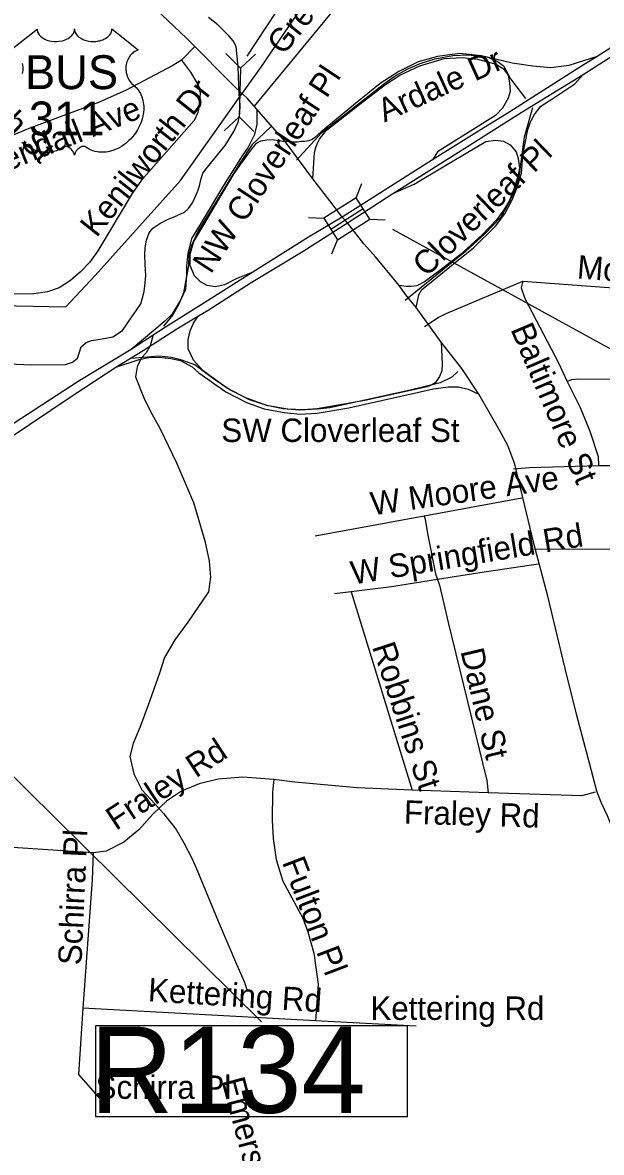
# Model space of a CAD drawing. Extents: x 1662474 to 1856135, y 779280 to 917889.
# Drawn here: x 1705150 to 1707499, y 792888 to 797474 of the extents above; entities that cross this region are included whole.
import ezdxf

# ---------------------------------------------------------------- set-up
doc = ezdxf.new("R2010")
doc.units = 0
for name, color, linetype in [('Exist Hydrographic Creek Single Shore', 7, 'Continuous'), ('Exist Hydrographic Misc Water Feature', 7, 'Continuous'), ('Exist Railroad Structure Bridge Number Label', 7, 'Continuous'), ('Exist Road Non-System Type 51', 7, 'Continuous'), ('Exist Road Non-System Type 51 Label', 7, 'Continuous'), ('Exist Road Primary Interstate Divided Center Attributed', 7, 'Continuous'), ('Exist Road Primary Interstate Ramp 1 Lane Attributed', 7, 'Continuous'), ('Exist Road Primary Interstate Structure Standard Bridge CELL', 7, 'Continuous'), ('Exist Road Primary Interstate Structure Standard Bridge Number Label', 7, 'Continuous'), ('Exist Road Primary US Shield CELL', 7, 'Continuous'), ('Exist Road Primary US Shield Number Label', 7, 'Continuous'), ('Exist Road Primary US Structure Pipe CELL', 7, 'Continuous'), ('Exist Road Primary US Structure Pipe Number Label', 7, 'Continuous'), ('Exist Road Primary US UnDivided 4 Lane Attributed', 7, 'Continuous'), ('Exist Utilities Electrical Transmission Line', 7, 'Continuous')]:
    doc.layers.add(name, color=color, linetype=linetype)

msp = doc.modelspace()

# ---------------------------------------------------------------- linework, layer by layer
at = {"layer": 'Exist Hydrographic Creek Single Shore'}
msp.add_lwpolyline([(1705094.1, 796088.5), (1705185.5, 796084.1), (1705324.2, 796085.9), (1705352.1, 796094.8), (1705371.8, 796111.3), (1705379.1, 796132.1), (1705387.8, 796157.2), (1705407.2, 796175.6), (1705429.8, 796183.2), (1705472, 796189.6), (1705516.4, 796198.8), (1705555.5, 796224.4), (1705593.4, 796280.1), (1705611.4, 796306.6), (1705628.8, 796331.8), (1705636.4, 796356.2), (1705642.4, 796383), (1705647.6, 796417.6), (1705649.8, 796447.3), (1705647.1, 796493.2), (1705645.5, 796531.2), (1705647.4, 796559.1), (1705652.4, 796590.3), (1705662.6, 796620.5), (1705678.1, 796638.9), (1705706.4, 796658.3), (1705738.2, 796674.3), (1705765, 796686.1), (1705806.4, 796705), (1705823, 796719.7), (1705839.5, 796742.8), (1705854, 796774.1), (1705860.8, 796791.4), (1705866.8, 796811.8), (1705873.6, 796840.4), (1705880.5, 796862.2), (1705894.9, 796880.4), (1705917.5, 796908.9), (1705972.2, 796974.6), (1706007, 797032.1), (1706024, 797070.1), (1706031.1, 797105.2), (1706032.1, 797141), (1706029, 797181.4), (1706024, 797293.8), (1706016.6, 797376.4), (1706003.8, 797399.5), (1705987.8, 797419.2), (1705941.4, 797464.6), (1705903.5, 797494.2)], dxfattribs=at)
at = {"layer": 'Exist Hydrographic Misc Water Feature'}
msp.add_lwpolyline([(1705677.5, 796201.8), (1705667.1, 796161.9), (1705650.9, 796134), (1705630.6, 796112.2), (1705614.3, 796076.4), (1705607.9, 796036.4), (1705641.2, 795950.1), (1705668.6, 795895.8), (1705706, 795827.4), (1705774.7, 795686.8), (1705843.1, 795526.1), (1705889.6, 795369.6), (1705906.9, 795287.4), (1705912.3, 795223.3), (1705903.7, 795163.4), (1705820.5, 795040.1), (1705767.9, 794968.6), (1705725.1, 794897), (1705704.6, 794833.2), (1705659.4, 794703.5), (1705628.5, 794619.8), (1705597.9, 794548), (1705585.4, 794494.1), (1705600.7, 794424), (1705634.1, 794359.7), (1705687.5, 794301.1), (1705721.1, 794262.8), (1705772.6, 794198.3), (1705804.1, 794144), (1705837.5, 794079.6), (1705857.1, 794035.4), (1705943.1, 793826.6), (1706017.5, 793651.8), (1706048.9, 793581.5), (1706060.5, 793545.4)], dxfattribs=at)
at = {"layer": 'Exist Railroad Structure Bridge Number Label'}
msp.add_line((1704279.7, 795236.4), (1706118.7, 793417.4), dxfattribs=at)
msp.add_lwpolyline([(1706711.4, 793401.9), (1705445.9, 793401.9), (1705445.9, 793033.1), (1706711.4, 793033.1)], close=True, dxfattribs=at)
at = {"layer": 'Exist Road Non-System Type 51'}
for p, q in [((1705849.5, 797378.5), (1705794.1, 797320.8)), ((1707180.1, 796423.7), (1708276.4, 796342.9)), ((1707487, 795675.6), (1707928.6, 795677.2)), ((1707175.1, 795543.6), (1706779.1, 795470.4)), ((1706779.1, 795470.4), (1706336.9, 795389.5)), ((1706482.8, 795163.6), (1706414.9, 795154.4)), ((1706482.8, 795163.6), (1706730, 794358.6)), ((1707038.9, 794346.8), (1706730, 794358.6)), ((1705436.1, 794104), (1704818.8, 794144.9)), ((1706338.6, 793421.6), (1705394.6, 793472.5)), ((1706746.4, 793399.6), (1706338.6, 793421.6))]:
    msp.add_line(p, q, dxfattribs=at)
for points in [[(1706090.1, 797134.4), (1706574.4, 797723.6)], [(1706261.5, 796915), (1706363.1, 797025.8), (1706619, 797227.4), (1706658.1, 797254.6), (1706710.4, 797284.5), (1706762.6, 797308.4), (1706822.6, 797326.8), (1706895.6, 797339.7), (1706957.1, 797343.4), (1707034.2, 797334.7), (1707075.6, 797317.4), (1707100.6, 797297.9), (1707129.5, 797245.4), (1707189.9, 797165.6)], [(1705794.1, 797320.8), (1705758.9, 797299.5), (1705570.1, 797199.5), (1705457.4, 797150.2), (1705172.1, 797042), (1705088.6, 797006.9), (1705065.2, 796992.2)], [(1705794.1, 797320.8), (1705830.6, 797272.7), (1705856.2, 797229.2), (1705870.1, 797190), (1705866.8, 797145.2), (1705861, 797109.2), (1705845.8, 797076.9), (1705632.6, 796834.4), (1705593.6, 796780.6), (1705455.5, 796547.5), (1705420.6, 796500), (1705385.1, 796462.8), (1705344, 796426.5), (1705298, 796397.7), (1705250.8, 796381.4), (1705195.4, 796373), (1705109.4, 796370.9)], [(1707218.5, 797128.4), (1707185.4, 797008.4), (1707161.8, 796838.1), (1707147.6, 796796.9), (1707122.6, 796742), (1707090.1, 796684.5), (1707026.1, 796615.8), (1706946.6, 796544.7), (1706702.5, 796345.4)], [(1706157.1, 797050.2), (1706081.8, 796979), (1706030.6, 796903.9), (1705860.5, 796625.8), (1705834.8, 796568.5), (1705824.2, 796530.8), (1705822.4, 796487.4), (1705801.9, 796377.2), (1705783.9, 796331.2), (1705759.1, 796287.2), (1705721.9, 796241.2)], [(1706780.4, 796240.2), (1706835.5, 796276.9), (1706868.4, 796292.4), (1707180.1, 796423.7)], [(1707180.1, 796423.7), (1707173.4, 796397.2), (1707188, 796353.4), (1707324, 796092.9), (1707359.9, 796017.6)], [(1706915.9, 796057.5), (1706891.6, 796034.9), (1706844.8, 796011.6), (1706716.9, 795980.6), (1706396.1, 795910.5), (1706346.6, 795904.2), (1706273.1, 795900.2), (1706205.6, 795906.4), (1706141.4, 795918.9), (1706058.6, 795948.9), (1705993.2, 795981.9), (1705929.5, 796023.1), (1705848.4, 796084.5), (1705791.4, 796104.5), (1705753.9, 796114.8), (1705703, 796120), (1705590.9, 796110.2)], [(1707359.9, 796017.6), (1707377.2, 796024.7), (1707405.1, 796027.4), (1708269.9, 796021.2)], [(1707359.9, 796017.6), (1707412.1, 795911.4), (1707451.5, 795815.5), (1707486.1, 795712.4), (1707487, 795675.6)], [(1707141.4, 795661.8), (1707207.4, 795668.5), (1707487, 795675.6)], [(1706779.1, 795470.4), (1706783.9, 795457.8), (1706792.8, 795400.4), (1706825.9, 795235.8), (1706833.4, 795212.7)], [(1707226.9, 795336.5), (1707595.6, 795337.6), (1707926.1, 795332.6)], [(1707241.4, 795275.4), (1707005.4, 795240.2), (1706833.4, 795212.7)], [(1706833.4, 795212.7), (1706646.9, 795183), (1706482.8, 795163.6)], [(1706833.4, 795212.7), (1706841.6, 795190.6), (1706876.5, 795039.2), (1707033.9, 794397.4), (1707038.9, 794346.8)], [(1706169.1, 794401.1), (1706042.9, 794411.1), (1705942.9, 794402.2), (1705866.5, 794384.4), (1705794.6, 794353.6), (1705734.2, 794314), (1705678.4, 794261.2), (1705621.4, 794196.4), (1705561, 794146.5), (1705488.9, 794111.1), (1705436.1, 794104)], [(1706169.1, 794401.1), (1706163.6, 794351), (1706162.1, 794235.8), (1706166.5, 794161.2), (1706178.6, 794077.2), (1706205.9, 793988.5), (1706286.5, 793838.1), (1706307.1, 793782.8), (1706331.6, 793695.9), (1706349.1, 793569.9), (1706338.6, 793421.6)], [(1706730, 794358.6), (1706507.4, 794367), (1706254.4, 794390.4), (1706169.1, 794401.1)], [(1707473.1, 794349.4), (1707419.8, 794334.4), (1707038.9, 794346.8)], [(1705436.1, 794104), (1705432.4, 793993.8), (1705394.6, 793472.5)], [(1705394.6, 793472.5), (1705377, 793204.5), (1705465.5, 793101.9)]]:
    msp.add_lwpolyline(points, dxfattribs=at)
at = {"layer": 'Exist Road Primary Interstate Divided Center Attributed'}
for points in [[(1709666.9, 798623), (1708893.7, 798183.2), (1707990.9, 797652.9), (1707728.8, 797493.2), (1707480.8, 797335.9)], [(1707424.4, 797262.9), (1707641.7, 797402.4), (1708004.6, 797607.9), (1708668.6, 797998.6), (1709099, 798238.3), (1709459.6, 798440.9)], [(1707480.8, 797335.9), (1707417.3, 797296.5), (1707111.8, 797102.8), (1707021.3, 797047.2), (1706812.9, 796916.8)], [(1706652.3, 796780.2), (1706944, 796963.5), (1707172.3, 797108.9), (1707424.4, 797262.9)], [(1706812.9, 796916.8), (1706446, 796684.4)], [(1706467.8, 796661.6), (1706570.4, 796727.6), (1706652.3, 796780.2)], [(1706446, 796684.4), (1706310.3, 796603.5), (1706083.5, 796461.3)], [(1705863.2, 796284), (1705902, 796306.9), (1706077.4, 796418.9), (1706288.5, 796545.8), (1706467.8, 796661.6)], [(1706083.5, 796461.3), (1705874.8, 796328.1), (1705729.6, 796237.3), (1705590.5, 796146.6)], [(1705527.4, 796074.5), (1705638.9, 796143.5), (1705775, 796231.3), (1705863.2, 796284)], [(1705590.5, 796146.6), (1705375.7, 796016.4), (1705051.1, 795807.8), (1704798.5, 795654.1), (1704424, 795449.2), (1704180.2, 795322.6)], [(1704178.7, 795254.8), (1704374.6, 795369.5), (1704483.3, 795420.2), (1704812.7, 795622.8), (1705087.3, 795781.1), (1705354.6, 795961.9), (1705527.4, 796074.5)]]:
    msp.add_lwpolyline(points, dxfattribs=at)
at = {"layer": 'Exist Road Primary Interstate Ramp 1 Lane Attributed'}
for points in [[(1707480.8, 797335.9), (1707365.9, 797299.6), (1707293.3, 797290.5), (1707220.7, 797296.5), (1707136, 797308.6), (1707012, 797338.9), (1706924.3, 797348), (1706833.6, 797335.9), (1706754.9, 797314.7), (1706676.3, 797275.3), (1706600.7, 797226.9), (1706500.9, 797145.2), (1706361.7, 797030.2), (1706334.3, 797005.8), (1706324.7, 796999.4), (1706309.6, 796993.9), (1706294.7, 796990.9), (1706280.1, 796990.9), (1706265.3, 796989.2), (1706249.9, 796989.2), (1706215, 796990.9)], [(1706327.2, 796840.2), (1706332.8, 796925.3), (1706334.1, 796947), (1706339.6, 796966.6), (1706345.6, 796981.5), (1706355, 797000.3), (1706383.5, 797036.8), (1706513.2, 797139.3), (1706621.9, 797223), (1706680.5, 797260.6), (1706762, 797298.3), (1706860.3, 797327.6), (1706933.5, 797331.8), (1706996.2, 797325.5), (1707071.5, 797304.6), (1707100.8, 797285.7), (1707119.6, 797260.6), (1707125.9, 797229.2), (1707128, 797193.7), (1707119.6, 797166.5), (1707096.6, 797126.7), (1707069.4, 797097.4), (1706834, 796949.3), (1706812.9, 796916.8)], [(1706747.4, 796317), (1706757.8, 796369.3), (1706770.4, 796390.2), (1706795.5, 796411.2), (1706883.3, 796482.3), (1706979.5, 796559.7), (1707069.4, 796647.6), (1707107.1, 796697.8), (1707136.3, 796754.3), (1707157.3, 796804.5), (1707174, 796863.1), (1707180.3, 796936.3), (1707200.3, 797040.6), (1707211.7, 797073.1), (1707227.1, 797100.4), (1707239.7, 797117), (1707253.4, 797134.7), (1707301.3, 797166), (1707390.2, 797225.3), (1707424.4, 797262.9)], [(1706100.4, 797123), (1706099.5, 797062), (1706090.2, 797019), (1706065.2, 796967.9), (1706041.1, 796933.4), (1705965.5, 796812.3), (1705874.8, 796661), (1705835.5, 796597.5), (1705820.3, 796536.9), (1705814.8, 796486.6), (1705814.8, 796452.7), (1705810.6, 796390.5), (1705790.8, 796346.7), (1705755.5, 796288.8), (1705726.6, 796261.5), (1705690.3, 796231.3), (1705590.5, 796146.6)], [(1706083.5, 796461.3), (1706016.9, 796434), (1705968.6, 796409.8), (1705932.3, 796400.8), (1705899, 796406.8), (1705871.8, 796421.9), (1705847.6, 796446.1), (1705829.4, 796488.5), (1705829.4, 796533.9), (1705844.5, 796585.4), (1705880.8, 796645.9), (1706007.9, 796860.7), (1706073.1, 796952.1), (1706098.6, 796984.8), (1706105.9, 796989.2), (1706116.8, 796993.9), (1706140.9, 796998.5), (1706161.9, 796999.1), (1706215, 796990.9)], [(1706652.3, 796780.2), (1706738.5, 796818.2), (1706856, 796888.3), (1707029.7, 796990.7), (1707069.4, 796997), (1707100.8, 796992.8), (1707128, 796978.2), (1707153.1, 796948.9), (1707161.4, 796921.7), (1707165.6, 796884), (1707161.4, 796854.7), (1707144.7, 796802.4), (1707125.9, 796752.2), (1707102.9, 796714.5), (1707073.6, 796674.8), (1707015.1, 796612), (1706927.2, 796532.5), (1706847.8, 796471.8), (1706780.8, 796421.6), (1706749.5, 796404.9), (1706726.5, 796402.8), (1706705.6, 796402.8), (1706678.4, 796407)], [(1706848.9, 796177.3), (1706852.8, 796088.4), (1706850.8, 796060.7), (1706841, 796037), (1706825.2, 796013.3), (1706811.3, 796003.4), (1706791.6, 795995.5), (1706538.7, 795940.1), (1706345.2, 795906.6), (1706287.9, 795902.6), (1706226.6, 795904.6), (1706145.6, 795918.4), (1706070.6, 795942.1), (1705977.7, 795991.5), (1705882.9, 796060.7), (1705843.4, 796104.2), (1705821.7, 796149.6), (1705821.7, 796187.2), (1705829.6, 796222.8), (1705843.4, 796254.4), (1705863.2, 796284)], [(1705527.4, 796074.5), (1705622.2, 796106.2), (1705661.7, 796114.1), (1705705.1, 796116.1), (1705750.6, 796110.1), (1705790.1, 796102.2), (1705837.5, 796076.5), (1705865.1, 796052.8), (1705973.8, 795975.7), (1706058.7, 795932.2), (1706129.8, 795906.6), (1706210.8, 795890.7), (1706276, 795884.8), (1706345.2, 795888.8), (1706473.5, 795910.5), (1706817.3, 795987.6), (1706876.5, 795995.5), (1706918, 795995.5), (1706957.5, 795985.6), (1707001, 795965.8)]]:
    msp.add_lwpolyline(points, dxfattribs=at)
at = {"layer": 'Exist Road Primary Interstate Structure Standard Bridge CELL'}
for p, q in [((1706503.8, 796762.9), (1706526.9, 796820.2)), ((1706400.1, 796635.7), (1706531.5, 796719.4)), ((1706310.5, 796682.7), (1706372.3, 796679.4)), ((1706558.9, 796676.4), (1706620.6, 796673.1)), ((1706404.9, 796534.6), (1706428, 796591.9))]:
    msp.add_line(p, q, dxfattribs=at)
msp.add_lwpolyline([(1706428, 796591.9), (1706559.4, 796675.6), (1706503.7, 796763.1), (1706372.3, 796679.4)], close=True, dxfattribs=at)
at = {"layer": 'Exist Road Primary Interstate Structure Standard Bridge Number Label'}
msp.add_line((1706650.8, 796635.3), (1708586.8, 795570.5), dxfattribs=at)
at = {"layer": 'Exist Road Primary US Shield CELL'}
for points in [[(1705101.8, 797363.2), (1705208.1, 797447.9), (1705208.3, 797443.5), (1705209.4, 797438.3), (1705210.2, 797435.6), (1705212.7, 797430.4), (1705216.7, 797424.3), (1705222.3, 797418.4), (1705228.6, 797413.2), (1705232.9, 797410.4), (1705240.1, 797406.5), (1705248.4, 797403), (1705257.5, 797400.4), (1705266.9, 797398.5), (1705277.1, 797397.4), (1705287.2, 797397.2), (1705298.1, 797398), (1705310.2, 797400.3), (1705315.8, 797401.8), (1705322, 797403.9), (1705327.8, 797406.3), (1705334.1, 797409.7), (1705339.2, 797413), (1705343.2, 797415.9), (1705348.8, 797421.3), (1705353.3, 797426.8), (1705355.2, 797430), (1705356.8, 797433), (1705359.1, 797439.4), (1705359.7, 797442.2), (1705360.1, 797448.1), (1705360.5, 797443.2), (1705361, 797440.1), (1705361.8, 797437.1), (1705363.1, 797433.9), (1705365.3, 797429.4), (1705367.8, 797425.6), (1705372.6, 797420), (1705375.5, 797417.2), (1705378.2, 797415), (1705385.5, 797410.1), (1705393.9, 797405.8), (1705398, 797404), (1705402.3, 797402.5), (1705407.7, 797400.8), (1705413.3, 797399.5), (1705418.8, 797398.6), (1705424.5, 797397.8), (1705430.2, 797397.3), (1705434.9, 797397.2), (1705440.7, 797397.3), (1705446.1, 797397.6), (1705451.5, 797398.2), (1705457.5, 797399.2), (1705462.4, 797400.3), (1705468.8, 797402), (1705474.6, 797404.1), (1705479.6, 797406.2), (1705486.2, 797409.7), (1705491.6, 797413), (1705495.5, 797416.2), (1705500.1, 797420.4), (1705504.5, 797425.5), (1705507.1, 797429.2), (1705508.9, 797433.1), (1705510.6, 797437.1), (1705511.6, 797441.4), (1705512.1, 797445.1), (1705512.2, 797448.2), (1705618.5, 797363.6), (1705616, 797362.6), (1705610.2, 797359.8), (1705605.6, 797357.1), (1705598.3, 797351.9), (1705595.2, 797349.1), (1705592.1, 797346.1), (1705589.2, 797343), (1705586.6, 797340.1), (1705583.5, 797335.8), (1705580.8, 797331.5), (1705578.1, 797326.8), (1705576.1, 797322.7), (1705572.8, 797314.2), (1705571.3, 797308.8), (1705570.3, 797304.2), (1705569, 797294.7), (1705568.7, 797290.2), (1705568.7, 797285.7), (1705569, 797281), (1705569.4, 797276.5), (1705570.2, 797271.8), (1705571, 797267.7), (1705572.3, 797262.6), (1705574.2, 797256.7), (1705576.5, 797250.9), (1705581.3, 797241.7), (1705587.6, 797232.3), (1705592, 797227), (1705596.4, 797222.5), (1705603, 797217), (1705606.5, 797213.8), (1705610.6, 797209.8), (1705617.3, 797202), (1705620, 797198.4), (1705622.7, 797194.3), (1705625.2, 797190.1), (1705627.7, 797185.6), (1705629.7, 797181.6), (1705633.5, 797172.5), (1705636.2, 797163.7), (1705637.5, 797159), (1705639.4, 797148.6), (1705640.2, 797143.4), (1705641, 797133.3), (1705641, 797121), (1705640.1, 797109.3), (1705637.9, 797095.6), (1705636.1, 797087.5), (1705633.3, 797078), (1705630.6, 797069.8), (1705625.7, 797057.7), (1705621.4, 797048.9), (1705615.8, 797038.6), (1705612, 797032.3), (1705607.6, 797025.7), (1705602, 797018), (1705595.4, 797009.9), (1705587.6, 797001.3), (1705581.3, 796994.9), (1705573, 796987.5), (1705567.9, 796983.4), (1705560.8, 796978), (1705551, 796971.4), (1705541.3, 796965.8), (1705533.1, 796961.6), (1705525.8, 796958.5), (1705516.4, 796954.9), (1705500.7, 796950.6), (1705495, 796949.4), (1705488.2, 796948.4), (1705481.9, 796947.8), (1705475.7, 796947.4), (1705467.5, 796947.4), (1705459.2, 796948), (1705451.5, 796949.1), (1705443.4, 796950.8), (1705434.9, 796953.3), (1705427.2, 796956.4), (1705419.4, 796960.2), (1705406.3, 796968.5), (1705402.5, 796970.5), (1705400.3, 796971.1), (1705395.2, 796971.3), (1705390.5, 796970.3), (1705385.6, 796968.3), (1705382.6, 796966.8), (1705378.7, 796964.2), (1705375.7, 796961.8), (1705372.1, 796958.4), (1705369.5, 796955.5), (1705367.6, 796953.2), (1705363.9, 796947.4), (1705362.6, 796944.6), (1705361.2, 796941), (1705360, 796935.8), (1705358.3, 796942.4), (1705356.4, 796946.8), (1705354.1, 796950.6), (1705351.8, 796953.9), (1705348.1, 796958.2), (1705344.8, 796961.4), (1705340.7, 796964.6), (1705336.5, 796967.2), (1705333, 796969), (1705329.9, 796970.2), (1705326.1, 796971.1), (1705322.9, 796971.4), (1705320.4, 796971.3), (1705316.8, 796970.5), (1705312, 796967), (1705307.5, 796963.9), (1705302.5, 796960.8), (1705296.6, 796957.7), (1705292.3, 796955.7), (1705287.1, 796953.7), (1705281.1, 796951.6), (1705274.6, 796950), (1705267.9, 796948.6), (1705262, 796947.7), (1705255.6, 796947.1), (1705249.9, 796946.9), (1705243.9, 796947), (1705238.4, 796947.4), (1705231.9, 796948), (1705223.9, 796949.2), (1705217.2, 796950.7), (1705210.2, 796952.6), (1705203, 796954.8), (1705195.2, 796957.8), (1705185.6, 796962), (1705178.9, 796965.5), (1705168.3, 796971.6), (1705155.8, 796980.2), (1705146.4, 796987.8)], [(1705149.2, 797266.9), (1705150.4, 797273.4), (1705151.3, 797279.5), (1705151.6, 797287.1), (1705151.4, 797293.3), (1705150.6, 797300.7), (1705149.2, 797307.7)]]:
    msp.add_lwpolyline(points, dxfattribs=at)
at = {"layer": 'Exist Road Primary US Structure Pipe CELL'}
for p, q in [((1705974.2, 797348), (1706033.4, 797289.4)), ((1706095.1, 797345.4), (1706033.4, 797289.4)), ((1706033.4, 797289.4), (1706029.1, 797091.1)), ((1705967.4, 797035.2), (1706029.1, 797091.1)), ((1706088.3, 797032.5), (1706029.1, 797091.1))]:
    msp.add_line(p, q, dxfattribs=at)
at = {"layer": 'Exist Road Primary US Structure Pipe Number Label'}
msp.add_line((1706061.4, 797337.6), (1707571.8, 799643.7), dxfattribs=at)
at = {"layer": 'Exist Road Primary US UnDivided 4 Lane Attributed'}
for points in [[(1706100.4, 797123), (1706060.3, 797167.7), (1706016.9, 797207.3), (1705814.5, 797411), (1705639.4, 797578.8), (1705459.4, 797750.1), (1705278.3, 797931.2), (1705123.4, 798090.8), (1705047.2, 798161.4), (1704992, 798206.4)], [(1706215, 796990.9), (1706134.9, 797082.1), (1706100.4, 797123)], [(1706327.2, 796840.2), (1706215, 796990.9)], [(1706446, 796684.4), (1706419.8, 796721), (1706327.2, 796840.2)], [(1706467.8, 796661.6), (1706446, 796684.4)], [(1706678.4, 796407), (1706583.7, 796521.8), (1706534.1, 796576.3), (1706467.8, 796661.6)], [(1706747.4, 796317), (1706705.1, 796368.4), (1706678.4, 796407)], [(1706848.9, 796177.3), (1706747.4, 796317)], [(1707001, 795965.8), (1706932.6, 796069.5), (1706848.9, 796177.3)], [(1709106, 792836.9), (1708244.2, 793579.6), (1707900.6, 793855.5), (1707749.3, 793987.3), (1707630, 794106.5), (1707578, 794164.6), (1707541.3, 794210.5), (1707523, 794253.3), (1707498.5, 794305.3), (1707480.1, 794354.2), (1707449.6, 794467.3), (1707397.5, 794666.1), (1707351.7, 794852.6), (1707281.3, 795146.1), (1707226.2, 795354), (1707146.7, 795681.2), (1707119.2, 795757.6), (1707085.5, 795818.8), (1707001, 795965.8)]]:
    msp.add_lwpolyline(points, dxfattribs=at)
at = {"layer": 'Exist Utilities Electrical Transmission Line'}
msp.add_lwpolyline([(1704303, 796746.1), (1704571.7, 796511.9), (1704785, 796331.3), (1705324.7, 796319.7), (1705444.5, 796447.9), (1705789.7, 796832.8), (1706014.1, 797147.6), (1706116.1, 797291.9), (1706424.4, 797745.2)], dxfattribs=at)

# ---------------------------------------------------------------- texts
at = {"layer": 'Exist Railroad Structure Bridge Number Label'}
msp.add_text('R134', height=350, dxfattribs=at).set_placement((1705422.6, 793048))
at = {"layer": 'Exist Road Non-System Type 51 Label'}
for s, rotation, p in [('Greenview Ter', 51.5037, (1706208.5, 797337.7)), ('Branch St', 315.1443, (1704825.8, 797291.6)), ('Ardale Dr', 24.378, (1706618.3, 797068)), ('NW Cloverleaf Pl', 56.6074, (1705913, 796450.1)), ('Kenilworth Dr', 51.6548, (1705449.6, 796597.9)), ('Kendall Ave', 21.8131, (1705008.7, 796838)), ('Cloverleaf Pl', 44.0774, (1706788.5, 796437.8)), ('Model Farm Rd', 355.5608, (1707397.4, 796435.5)), ('Baltimore St', 293.0732, (1707128.5, 796229.3)), ('W Moore Ave', 8.1348, (1706568.8, 795473)), ('W Springfield Rd', 9.4678, (1706489.8, 795192.2)), ('Robbins St', 288.1822, (1706567, 794940.7)), ('Dane St', 283.322, (1706926, 794922.8)), ('Fraley Rd', 33.3642, (1705528.5, 794191.8)), ('Fraley Rd', 358.3054, (1706696.1, 794222.3)), ('Schirra Pl', 87.4252, (1705388.3, 793646.4)), ('Fulton Pl', 290.895, (1706201.5, 794066.1)), ('Kettering Rd', 356.3547, (1705656.6, 793501.4)), ('Emerson St', 284.8945, (1705956.1, 793179.2))]:
    msp.add_text(s, height=95, rotation=rotation, dxfattribs=at).set_placement(p)
for s, p in [('SW Cloverleaf St', (1705956, 795771.5)), ('Kettering Rd', (1706560.9, 793425.5)), ('Schirra Pl', (1705445.9, 793105))]:
    msp.add_text(s, height=95, dxfattribs=at).set_placement(p)
at = {"layer": 'Exist Road Primary US Shield Number Label'}
for s, p in [('BUS', (1705159, 797203.8)), ('311', (1705175.2, 797015.9))]:
    msp.add_text(s, height=137.5, dxfattribs=at).set_placement(p)

doc.saveas('drawing.dxf')
